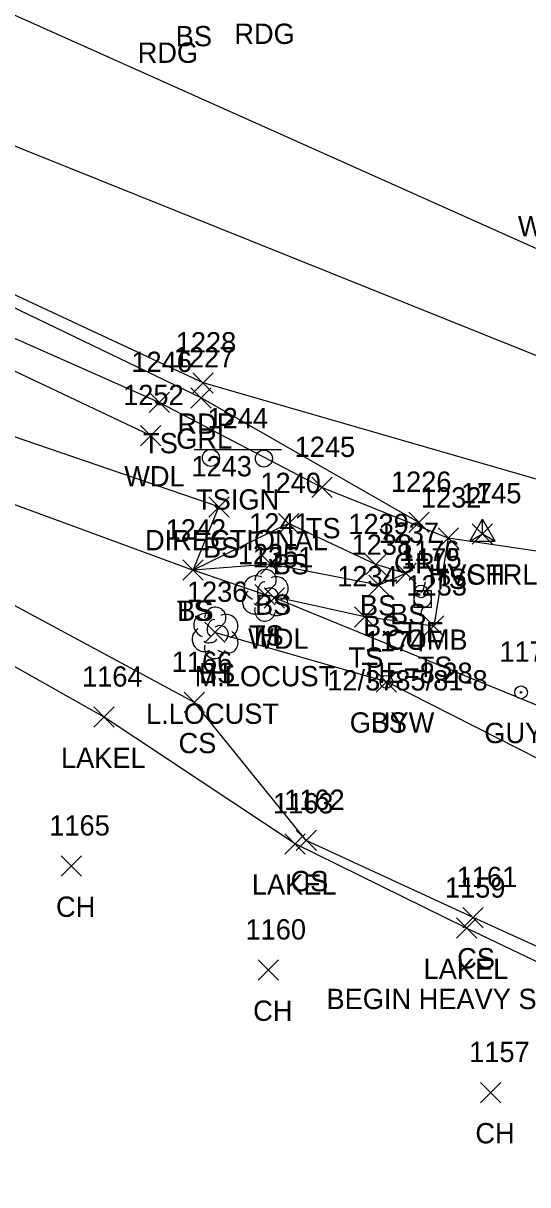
# Model space of a CAD drawing. Extents: x 1401404 to 1403982, y 557481 to 559873.
# Drawn here: x 1403304.1 to 1403353.7, y 558523.7 to 558637.9 of the extents above; entities that cross this region are included whole.
import ezdxf

# ---------------------------------------------------------------- set-up
doc = ezdxf.new("R2010")
doc.units = 0
for name, color, linetype in [('C_A', 7, 'Continuous'), ('C_C', 7, 'Continuous'), ('C_I', 7, 'Continuous'), ('CBP', 7, 'Continuous'), ('CPSM', 7, 'Continuous'), ('L_A', 7, 'Continuous'), ('L_C', 7, 'Continuous'), ('L_I', 7, 'Continuous'), ('L_TIC', 7, 'Continuous'), ('LAWA', 7, 'Continuous'), ('LAWE', 7, 'Continuous'), ('LELB', 7, 'Continuous'), ('LTD', 7, 'Continuous'), ('P_A', 7, 'Continuous'), ('P_I', 7, 'Continuous'), ('P_TIC', 7, 'Continuous'), ('PET', 7, 'Continuous'), ('PRC', 7, 'Continuous'), ('R_A', 7, 'Continuous'), ('R_I', 7, 'Continuous'), ('R_TIC', 7, 'Continuous'), ('RGR', 7, 'Continuous'), ('S_A', 7, 'Continuous'), ('S_C', 7, 'Continuous'), ('S_I', 7, 'Continuous'), ('SSGN', 7, 'Continuous'), ('U_A', 7, 'Continuous'), ('U_C', 7, 'Continuous'), ('U_I', 7, 'Continuous'), ('UP', 7, 'Continuous'), ('UPGW', 7, 'Continuous')]:
    doc.layers.add(name, color=color, linetype=linetype)

msp = doc.modelspace()

# ---------------------------------------------------------------- linework, layer by layer
at = {"layer": 'CBP'}
for radius in [0.625, 0.0833]:
    msp.add_circle((1403343.26, 558582.03), radius, dxfattribs=at)
at = {"layer": 'CPSM'}
for p, q in [((1403348.04, 558586.98), (1403349.29, 558589.15)), ((1403350.54, 558586.98), (1403349.29, 558589.15)), ((1403349.29, 558587.7), (1403349.29, 558589.15)), ((1403348.04, 558586.98), (1403349.29, 558587.7)), ((1403348.04, 558586.98), (1403350.54, 558586.98)), ((1403349.29, 558587.7), (1403349.29, 558587.7)), ((1403349.29, 558587.7), (1403350.54, 558586.98))]:
    msp.add_line(p, q, dxfattribs=at)
at = {"layer": 'L_TIC'}
for points in [[(1403316.51, 558599.62), (1403318.51, 558601.62)], [(1403318.51, 558599.62), (1403316.51, 558601.62)], [(1403315.66, 558596.36), (1403317.66, 558598.36)], [(1403317.66, 558596.36), (1403315.66, 558598.36)], [(1403332.51, 558591.26), (1403334.51, 558593.26)], [(1403334.51, 558591.26), (1403332.51, 558593.26)], [(1403322.37, 558589.35), (1403324.37, 558591.35)], [(1403324.37, 558589.35), (1403322.37, 558591.35)], [(1403329.23, 558587.71), (1403331.23, 558589.71)], [(1403331.23, 558587.71), (1403329.23, 558589.71)], [(1403344.93, 558586.28), (1403346.93, 558588.28)], [(1403346.93, 558586.28), (1403344.93, 558588.28)], [(1403344.93, 558586.28), (1403346.93, 558588.28)], [(1403346.93, 558586.28), (1403344.93, 558588.28)], [(1403348.29, 558586.7), (1403350.29, 558588.7)], [(1403350.29, 558586.7), (1403348.29, 558588.7)], [(1403327.48, 558583.73), (1403329.48, 558585.73)], [(1403329.48, 558583.73), (1403327.48, 558585.73)], [(1403319.84, 558583.14), (1403321.84, 558585.14)], [(1403321.84, 558583.14), (1403319.84, 558585.14)], [(1403319.84, 558583.14), (1403321.84, 558585.14)], [(1403321.84, 558583.14), (1403319.84, 558585.14)], [(1403319.84, 558583.14), (1403321.84, 558585.14)], [(1403321.84, 558583.14), (1403319.84, 558585.14)], [(1403337.8, 558583.67), (1403339.8, 558585.67)], [(1403339.8, 558583.67), (1403337.8, 558585.67)], [(1403340.76, 558582.81), (1403342.76, 558584.81)], [(1403342.76, 558582.81), (1403340.76, 558584.81)], [(1403340.76, 558582.81), (1403342.76, 558584.81)], [(1403342.76, 558582.81), (1403340.76, 558584.81)], [(1403338.11, 558581.64), (1403340.11, 558583.64)], [(1403340.11, 558581.64), (1403338.11, 558583.64)], [(1403326.92, 558580.7), (1403328.92, 558582.7)], [(1403328.92, 558580.7), (1403326.92, 558582.7)], [(1403327.83, 558580.39), (1403329.83, 558582.39)], [(1403329.83, 558580.39), (1403327.83, 558582.39)], [(1403336.71, 558578.53), (1403338.71, 558580.53)], [(1403338.71, 558578.53), (1403336.71, 558580.53)], [(1403321.98, 558577.01), (1403323.98, 558579.01)], [(1403323.98, 558577.01), (1403321.98, 558579.01)], [(1403343.5, 558577.63), (1403345.5, 558579.63)], [(1403345.5, 558577.63), (1403343.5, 558579.63)], [(1403338.85, 558572.14), (1403340.85, 558574.14)], [(1403340.85, 558572.14), (1403338.85, 558574.14)], [(1403319.97, 558570.12), (1403321.97, 558572.12)], [(1403321.97, 558570.12), (1403319.97, 558572.12)], [(1403311.09, 558568.67), (1403313.09, 558570.67)], [(1403313.09, 558568.67), (1403311.09, 558570.67)], [(1403330.97, 558556.54), (1403332.97, 558558.54)], [(1403332.97, 558556.54), (1403330.97, 558558.54)], [(1403329.86, 558556.2), (1403331.86, 558558.2)], [(1403331.86, 558556.2), (1403329.86, 558558.2)], [(1403307.87, 558554.02), (1403309.87, 558556.02)], [(1403309.87, 558554.02), (1403307.87, 558556.02)], [(1403347.36, 558548.95), (1403349.36, 558550.95)], [(1403349.36, 558548.95), (1403347.36, 558550.95)], [(1403346.73, 558547.91), (1403348.73, 558549.91)], [(1403348.73, 558547.91), (1403346.73, 558549.91)], [(1403327.25, 558543.79), (1403329.25, 558545.79)], [(1403329.25, 558543.79), (1403327.25, 558545.79)], [(1403349.1, 558531.74), (1403351.1, 558533.74)], [(1403351.1, 558531.74), (1403349.1, 558533.74)]]:
    msp.add_lwpolyline(points, dxfattribs=at)
at = {"layer": 'LAWA'}
for points in [[(1403316.66, 558597.36), (1403281.73, 558613.91), (1403272.54, 558615.21), (1403248.23, 558629.23), (1403213.48, 558654.18), (1403180.64, 558681.31), (1403143.75, 558710.34), (1403107.91, 558739.1), (1403071.69, 558772.58), (1403068.31, 558766.93), (1403071.88, 558756.66), (1403070.51, 558749.44)], [(1403486.9, 558558.65), (1403436.49, 558562.32), (1403410.5, 558564.81), (1403382.81, 558572.6), (1403367.26, 558569.55), (1403356.36, 558570.14), (1403328.83, 558581.39)]]:
    msp.add_lwpolyline(points, dxfattribs=at)
at = {"layer": 'LAWE'}
msp.add_lwpolyline([(1403696.34, 558534.54), (1403680.72, 558542.26), (1403669.4, 558548.58), (1403629.67, 558556.01), (1403603.5, 558551.35), (1403567.18, 558559.29), (1403520.13, 558560.76), (1403486.9, 558558.65), (1403434.25, 558550.99), (1403410.67, 558547.97), (1403397.83, 558540.52), (1403383.21, 558537.84), (1403361.63, 558542.24), (1403347.73, 558548.91), (1403330.86, 558557.2), (1403312.09, 558569.67), (1403266.36, 558595.5), (1403259.7, 558589.6), (1403257.9, 558590.94)], dxfattribs=at)
at = {"layer": 'LELB'}
for points in [[(1403567.19, 558568.67), (1403521.33, 558570.05), (1403484.77, 558571.48), (1403436.83, 558574.71), (1403390.35, 558579.88), (1403360.17, 558585.19), (1403345.93, 558587.28), (1403333.51, 558592.26), (1403317.51, 558600.62), (1403299, 558608.83), (1403282.94, 558617.97), (1403248.09, 558638.93), (1403217.12, 558660.94), (1403185.33, 558684.7), (1403148.79, 558715.46), (1403112.06, 558744.49), (1403074.23, 558776.66), (1403055.65, 558783.75), (1403043.18, 558796.21), (1403041.06, 558801.07)], [(1403341.76, 558583.81), (1403338.8, 558584.67), (1403330.23, 558588.71), (1403320.84, 558584.14), (1403323.37, 558590.35), (1403277.97, 558605.9), (1403273.27, 558609.23), (1403246.67, 558626.12)], [(1403320.97, 558571.12), (1403269.36, 558598.93)], [(1403281.79, 558598.48), (1403320.84, 558584.14)], [(1403345.93, 558587.28), (1403344.5, 558578.63), (1403337.71, 558579.53), (1403327.92, 558581.7), (1403320.84, 558584.14)], [(1403341.76, 558583.81), (1403339.11, 558582.64), (1403328.48, 558584.73), (1403320.84, 558584.14)], [(1403725.58, 558523.67), (1403722.74, 558539.45), (1403706.56, 558549.47), (1403693.69, 558551), (1403674.49, 558552.83), (1403667, 558555.83), (1403630.82, 558558.09), (1403603.44, 558554.21), (1403567.5, 558561.8), (1403520.15, 558563.09), (1403486.24, 558561.72), (1403436.49, 558562.32), (1403409.67, 558557.93), (1403401.43, 558554.22), (1403392.6, 558552.11), (1403381.98, 558552.19), (1403374.37, 558554.61), (1403368.01, 558558.84), (1403339.85, 558573.14), (1403322.98, 558578.01)], [(1403383.74, 558539.09), (1403362.85, 558543.36), (1403348.36, 558549.95), (1403331.97, 558557.54), (1403320.97, 558571.12)]]:
    msp.add_lwpolyline(points, dxfattribs=at)
at = {"layer": 'LTD'}
for p, q in [((1403327.92, 558581.7), (1403327.92, 558581.7)), ((1403327.92, 558581.7), (1403327.92, 558581.7)), ((1403322.98, 558578.01), (1403322.98, 558578.01)), ((1403322.98, 558578.01), (1403322.98, 558578.01))]:
    msp.add_line(p, q, dxfattribs=at)
for centre in [(1403327.97, 558583.14), (1403323.02, 558579.44)]:
    msp.add_arc(centre, 1.05, 335.5272, 180.9563, dxfattribs=at)
for centre, major_axis, ratio, start_param, end_param in [((1403327.13, 558582.37), (1.21, -0.51), 0.895232, 1.570796, 4.712389), ((1403328.96, 558582.29), (-1.14, -0.48), 0.949671, 1.570796, 4.712389), ((1403327.71, 558582.16), (-0.208, -0.792), 0.645439, 3.141593, 6.283185), ((1403328.42, 558581.54), (-0.5, 0.667), 0.989748, 3.141593, 6.283185), ((1403326.84, 558580.99), (0.58, -1.04), 0.959034, 3.141593, 6.283185), ((1403328.92, 558580.87), (-1.09, 0.79), 0.841452, 1.570796, 4.712389), ((1403322.19, 558578.67), (1.21, -0.51), 0.895232, 1.570796, 4.712389), ((1403327.92, 558580.2), (0.26, 1.06), 0.942809, 1.570796, 4.712389), ((1403327.46, 558580.95), (-0.625, -0.083), 0.423636, 0, 3.141593), ((1403322.77, 558578.46), (-0.208, -0.792), 0.645439, 3.141593, 6.283185), ((1403324.02, 558578.59), (-1.14, -0.48), 0.949671, 1.570796, 4.712389), ((1403321.89, 558577.3), (0.58, -1.04), 0.959034, 3.141593, 6.283185), ((1403323.48, 558577.84), (-0.5, 0.667), 0.989748, 3.141593, 6.283185), ((1403323.98, 558577.17), (-1.09, 0.79), 0.841452, 1.570796, 4.712389), ((1403322.98, 558576.51), (0.26, 1.06), 0.942809, 1.570796, 4.712389), ((1403322.52, 558577.26), (-0.625, -0.083), 0.423636, 0, 3.141593)]:
    msp.add_ellipse(centre, major_axis=major_axis, ratio=ratio, start_param=start_param, end_param=end_param, dxfattribs=at)
at = {"layer": 'P_TIC'}
for points in [[(1403320.82, 558601.54), (1403322.82, 558603.54)], [(1403322.82, 558601.54), (1403320.82, 558603.54)]]:
    msp.add_lwpolyline(points, dxfattribs=at)
at = {"layer": 'PET'}
for points in [[(1403567.32, 558571.16), (1403521.05, 558571.89), (1403485.08, 558573.95), (1403437.34, 558577.29), (1403390.93, 558583.55), (1403361.61, 558591.03), (1403321.82, 558602.54), (1403283.74, 558620.33), (1403244.19, 558645.3), (1403219.22, 558663.61), (1403205.44, 558672.12), (1403186.06, 558688.41), (1403150.64, 558718.11), (1403114.18, 558748.06), (1403076.2, 558780.03), (1403043.94, 558806.7), (1402997.13, 558841.77), (1402954.25, 558870.69), (1402915.87, 558893.53), (1402876.18, 558915.42), (1402801.33, 558955.21), (1402766.49, 558972.95)], [(1403552.49, 558594.8), (1403524.49, 558596.02), (1403520.25, 558595.63), (1403487.06, 558596.83), (1403440.08, 558600.18), (1403395.05, 558605.77), (1403363.07, 558611.97), (1403293.66, 558643.04), (1403283.54, 558648.26), (1403256.86, 558665.1), (1403232.94, 558682.45), (1403201.28, 558707.26), (1403164.55, 558736.67), (1403129.25, 558765.78)]]:
    msp.add_lwpolyline(points, dxfattribs=at)
at = {"layer": 'PRC'}
msp.add_lwpolyline([(1403567.87, 558582.77), (1403521.72, 558584.55), (1403486.23, 558585.01), (1403438.97, 558588.43), (1403393.1, 558594.9), (1403360.83, 558602.71), (1403288.92, 558631.6), (1403250.3, 558655.21), (1403225.89, 558672.35), (1403193.37, 558698.04), (1403157.15, 558726.96), (1403121.95, 558757.26), (1403083.22, 558789.98), (1403051.1, 558815.94), (1403004.27, 558851.49), (1402960.21, 558880.82), (1402921.63, 558903.82), (1402881.32, 558926.06), (1402807.32, 558964.73), (1402770.83, 558983.44)], dxfattribs=at)
at = {"layer": 'R_TIC'}
for points in [[(1403320.63, 558600.07), (1403322.63, 558602.07)], [(1403322.63, 558600.07), (1403320.63, 558602.07)], [(1403342.04, 558587.83), (1403344.04, 558589.83)], [(1403344.04, 558587.83), (1403342.04, 558589.83)]]:
    msp.add_lwpolyline(points, dxfattribs=at)
at = {"layer": 'RGR'}
msp.add_lwpolyline([(1403343.04, 558588.83), (1403321.63, 558601.07), (1403283.23, 558619.58), (1403243.1, 558643.52), (1403218.12, 558661.74), (1403185.48, 558687.65), (1403149.87, 558716.9), (1403113.35, 558746.32), (1403075.03, 558778.37), (1403064.92, 558785.89), (1403057.13, 558787.17)], dxfattribs=at)
at = {"layer": 'SSGN'}
for p, q in [((1403320.93, 558596), (1403329.53, 558596)), ((1403324.95, 558595.1), (1403324.95, 558595.1))]:
    msp.add_line(p, q, dxfattribs=at)
for centre in [(1403322.59, 558595.17), (1403327.8, 558595.1)]:
    msp.add_circle(centre, 0.833, dxfattribs=at)
at = {"layer": 'UP'}
for p, q in [((1403343.66, 558582.95), (1403343.41, 558582.12)), ((1403342.58, 558580.45), (1403342.58, 558582.12)), ((1403342.58, 558582.12), (1403344.25, 558582.12)), ((1403343.41, 558581.29), (1403343.41, 558581.29)), ((1403344.25, 558582.12), (1403344.25, 558580.45)), ((1403344.25, 558580.45), (1403342.58, 558580.45)), ((1403343.16, 558579.62), (1403343.41, 558580.45))]:
    msp.add_line(p, q, dxfattribs=at)
msp.add_circle((1403343.41, 558581.29), 0.833, dxfattribs=at)
at = {"layer": 'UPGW'}
for centre, radius in [((1403339.85, 558573.14), 0.625), ((1403339.85, 558573.14), 0.0833), ((1403353.08, 558572.11), 0.625), ((1403353.08, 558572.11), 0.0833)]:
    msp.add_circle(centre, radius, dxfattribs=at)

# ---------------------------------------------------------------- texts
at = {"layer": 'C_A'}
for s, p in [('HVCTRL', (1403343.99, 558582.7)), ('TIE', (1403341.34, 558577.03))]:
    msp.add_text(s, height=2, dxfattribs=at).set_placement(p)
at = {"layer": 'C_C'}
msp.add_text('TIE=8.28', height=2, dxfattribs=at).set_placement((1403337.39, 558573.03))
at = {"layer": 'C_I'}
for s, p in [('7', (1403348.73, 558590.7)), ('1176', (1403341.08, 558585.03))]:
    msp.add_text(s, height=2, dxfattribs=at).set_placement(p)
at = {"layer": 'L_A'}
for s, p in [('BS', (1403319.13, 558635.66)), ('TS', (1403315.92, 558595.62)), ('WDL', (1403314.07, 558592.36)), ('TS', (1403331.92, 558587.26)), ('BS', (1403321.81, 558585.35)), ('BS', (1403328.67, 558583.71)), ('SH', (1403347.78, 558582.7)), ('TS', (1403344.34, 558582.28)), ('TS', (1403344.34, 558582.28)), ('TS', (1403319.24, 558579.14)), ('BS', (1403319.28, 558579.14)), ('BS', (1403319.28, 558579.14)), ('BS', (1403326.92, 558579.73)), ('BS', (1403337.24, 558579.67)), ('BS', (1403340.2, 558578.81)), ('BS', (1403340.2, 558578.81)), ('BS', (1403337.55, 558577.64)), ('WDL', (1403326.25, 558576.39)), ('TS', (1403326.33, 558576.7)), ('H', (1403327.36, 558576.7)), ('TS', (1403336.12, 558574.53)), ('TS', (1403342.91, 558573.63)), ('BS', (1403321.42, 558573.01)), ('H', (1403322.41, 558573.01)), ('BS', (1403338.29, 558568.14)), ('CS', (1403319.41, 558566.12)), ('LAKEL', (1403307.85, 558564.67)), ('LAKEL', (1403326.62, 558552.2)), ('CS', (1403330.41, 558552.54)), ('CH', (1403307.36, 558550.02)), ('CS', (1403346.8, 558544.95)), ('LAKEL', (1403343.5, 558543.91)), ('CH', (1403326.74, 558539.79)), ('CH', (1403348.59, 558527.74))]:
    msp.add_text(s, height=2, dxfattribs=at).set_placement(p)
at = {"layer": 'L_C'}
for s, p in [('M.LOCUST', (1403320.99, 558572.7)), ('L.LOCUST', (1403316.21, 558569.01)), ('BEGIN HEAVY SLIDE', (1403333.95, 558540.95))]:
    msp.add_text(s, height=2, dxfattribs=at).set_placement(p)
at = {"layer": 'L_I'}
for s, p in [('1246', (1403314.77, 558603.62)), ('1252', (1403313.96, 558600.36)), ('1245', (1403330.82, 558595.26)), ('1243', (1403320.67, 558593.35)), ('1240', (1403327.45, 558591.71)), ('1145', (1403347.17, 558590.7)), ('1232', (1403343.23, 558590.28)), ('1232', (1403343.23, 558590.28)), ('1242', (1403318.14, 558587.14)), ('1242', (1403318.14, 558587.14)), ('1242', (1403318.14, 558587.14)), ('1241', (1403326.35, 558587.73)), ('1239', (1403336.1, 558587.67)), ('1237', (1403339.06, 558586.81)), ('1237', (1403339.06, 558586.81)), ('1238', (1403336.42, 558585.64)), ('1235', (1403325.23, 558584.7)), ('1235', (1403325.23, 558584.7)), ('1251', (1403326.7, 558584.39)), ('1234', (1403335.01, 558582.53)), ('1233', (1403341.81, 558581.63)), ('1236', (1403320.23, 558581.01)), ('1236', (1403320.23, 558581.01)), ('1174', (1403337.72, 558576.14)), ('1166', (1403318.74, 558574.12)), ('1164', (1403309.92, 558572.67)), ('1163', (1403328.69, 558560.2)), ('1162', (1403329.79, 558560.54)), ('1165', (1403306.7, 558558.02)), ('1161', (1403346.75, 558552.95)), ('1159', (1403345.6, 558551.91)), ('1160', (1403325.99, 558547.79)), ('1157', (1403347.98, 558535.74))]:
    msp.add_text(s, height=2, dxfattribs=at).set_placement(p)
at = {"layer": 'P_A'}
for s, p in [('RDG', (1403324.89, 558635.89)), ('RDG', (1403315.39, 558634.03)), ('RDP', (1403319.31, 558597.54))]:
    msp.add_text(s, height=2, dxfattribs=at).set_placement(p)
at = {"layer": 'P_I'}
msp.add_text('1228', height=2, dxfattribs=at).set_placement((1403319.13, 558605.54))
at = {"layer": 'R_A'}
for p in [(1403319.18, 558596.07), (1403340.59, 558583.83)]:
    msp.add_text('GRL', height=2, dxfattribs=at).set_placement(p)
at = {"layer": 'R_I'}
for s, p in [('1227', (1403318.94, 558604.07)), ('1226', (1403340.29, 558591.83))]:
    msp.add_text(s, height=2, dxfattribs=at).set_placement(p)
at = {"layer": 'S_A'}
msp.add_text('TSIGN', height=2, dxfattribs=at).set_placement((1403321.13, 558590.08))
at = {"layer": 'S_C'}
for s, p in [('WHITNEY CREEK ROAD', (1403352.77, 558616.98)), ('DIRECTIONAL', (1403316.11, 558586.08))]:
    msp.add_text(s, height=2, dxfattribs=at).set_placement(p)
at = {"layer": 'S_I'}
msp.add_text('1244', height=2, dxfattribs=at).set_placement((1403322.25, 558598.08))
at = {"layer": 'U_A'}
for s, p in [('COMB', (1403339.8, 558576.29)), ('GUYW', (1403336.24, 558568.14)), ('GUYW', (1403349.47, 558567.11))]:
    msp.add_text(s, height=2, dxfattribs=at).set_placement(p)
at = {"layer": 'U_C'}
msp.add_text('12/3785/81-8', height=2, dxfattribs=at).set_placement((1403334.03, 558572.29))
at = {"layer": 'U_I'}
for s, p in [('1175', (1403341.29, 558584.29)), ('1174', (1403337.72, 558576.14)), ('1173', (1403350.95, 558575.11))]:
    msp.add_text(s, height=2, dxfattribs=at).set_placement(p)

doc.saveas('drawing.dxf')
